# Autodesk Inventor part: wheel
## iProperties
Author: Administrator
Created: 2000-12
Part Number: wheel
Document SubType Name: Modeling
Designer: Administrator
Control State: 0
Master: False
Checked Out: False
PropertySet Name: Design Tracking Control
Shininess: 0.0
PropertySet Name: _Private Model Information
Density: 0.0
Volumn: 0.0
Area: 0.0
PropertySet Name: Model Information
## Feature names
1. Revolution1
